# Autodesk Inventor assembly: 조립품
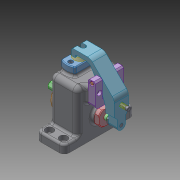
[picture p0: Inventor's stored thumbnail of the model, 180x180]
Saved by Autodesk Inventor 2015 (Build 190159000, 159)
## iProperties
Created: 2023-12
Part Number: 조립품
Document SubType Name: Assembly
Designer: 104-1
Author: 104-1
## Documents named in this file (14)
- C:\Users\104-1\Desktop\731208V1007\조립품.iam
- C:\Users\104-1\Desktop\731208V1007\본체.ipt
- C:\Users\104-1\Desktop\731208V1007\가이드 부시.ipt
- C:\Users\104-1\Desktop\731208V1007\고정대.ipt
- C:\Users\104-1\Desktop\731208V1007\브라켓.ipt
- C:\Users\104-1\Desktop\731208V1007\스프링.ipt
- C:\Users\104-1\Desktop\731208V1007\육각 머리 볼트 M6 x 12.ipt
- C:\Users\104-1\Desktop\731208V1007\육각 소켓 머리 볼트 M3 x 8.ipt
- C:\Users\104-1\Desktop\731208V1007\육각 소켓 머리 볼트 M3 x 30.ipt
- C:\Users\104-1\Desktop\731208V1007\조절 부시.ipt
- C:\Users\104-1\Desktop\731208V1007\클램프 샤프트.ipt
- C:\Users\104-1\Desktop\731208V1007\클램프.ipt
- C:\Users\104-1\Desktop\731208V1007\핀.ipt
- C:\Users\104-1\Desktop\731208V1007\가공품.ipt
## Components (4 placed, 4 different names)
1. 가이드 부시:1
2. 고정대:1
3. 핀:1
4. 가공품:1
